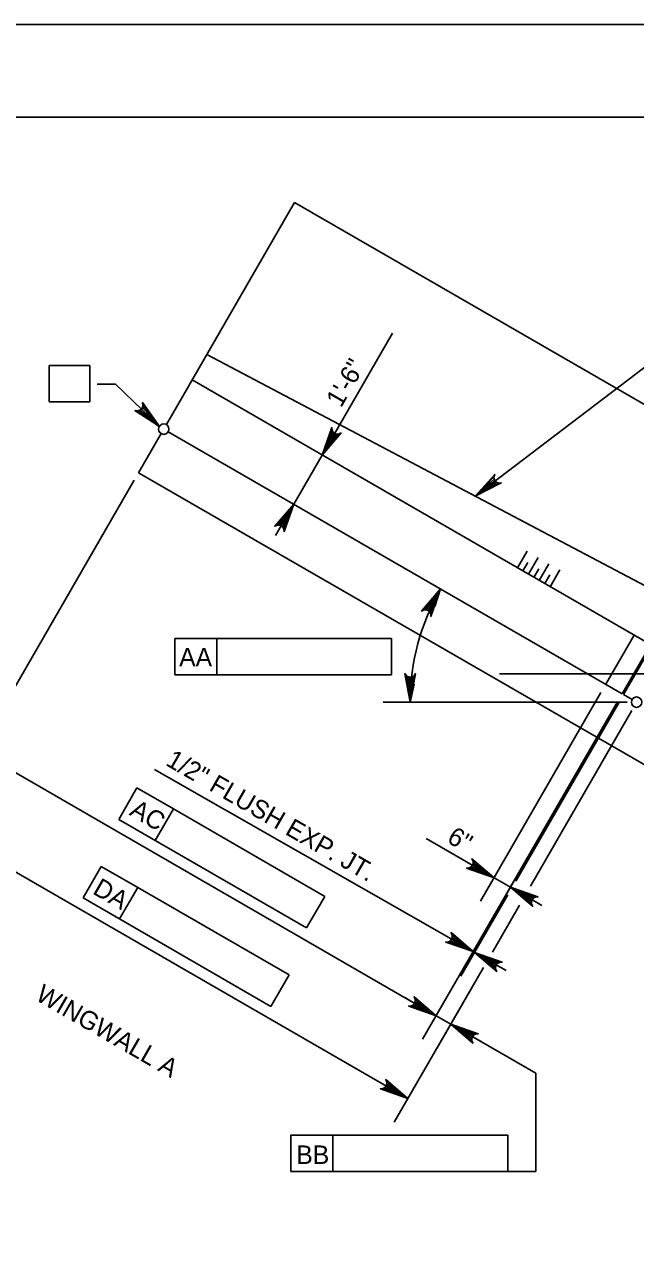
# Model space of a CAD drawing. Extents: x 638255 to 640306, y 296059 to 298435.
# Drawn here: x 638520.2 to 638619.4, y 298235.1 to 298435.5 of the extents above; entities that cross this region are included whole.
import ezdxf

# ---------------------------------------------------------------- set-up
doc = ezdxf.new("R2010")
doc.units = 0
for name, color, linetype in [('2', 7, 'Continuous'), ('Level 10', 7, 'Continuous'), ('Level 2', 7, 'Continuous'), ('Level 3', 7, 'Continuous'), ('PLT-BNDY', 7, 'Continuous')]:
    doc.layers.add(name, color=color, linetype=linetype)

msp = doc.modelspace()

# ---------------------------------------------------------------- linework, layer by layer
at = {"layer": '2'}
msp.add_line((638475.46, 298420.46), (639261.46, 298420.46), dxfattribs=at)
at = {"layer": 'Level 10'}
for p, q in [((638543.25, 298370.52), (638564.06, 298406.56)), ((638646.07, 298359.21), (638564.06, 298406.56)), ((638625.9, 298341.75), (638549.83, 298381.91)), ((638621.87, 298334.78), (638547.43, 298377.76)), ((638538.73, 298362.69), (638542.4, 298369.05)), ((638617.26, 298326.8), (638543.56, 298369.36)), ((638621.86, 298314.7), (638538.73, 298362.69)), ((638625.9, 298341.75), (638617.26, 298326.8)), ((638625.6, 298340.74), (638617.48, 298326.67)), ((638619.21, 298336.31), (638614.6, 298328.34)), ((638597.38, 298330.05), (638862.07, 298330.05)), ((638618.89, 298325.87), (638617.48, 298326.67))]:
    msp.add_line(p, q, dxfattribs=at)
at = {"layer": 'Level 2'}
for p, q in [((638600.27, 298347.25), (638601.85, 298349.98)), ((638602.05, 298346.22), (638603.62, 298348.95)), ((638601.16, 298346.74), (638601.97, 298348.14)), ((638602.93, 298345.71), (638603.74, 298347.11)), ((638603.82, 298345.2), (638605.39, 298347.93)), ((638604.7, 298344.69), (638605.51, 298346.09)), ((638605.59, 298344.18), (638607.17, 298346.91))]:
    msp.add_line(p, q, dxfattribs=at)
at = {"layer": 'Level 3'}
for p, q in [((638568.54, 298365.57), (638579.97, 298385.34)), ((638524.23, 298374.2), (638524.23, 298380.1)), ((638524.23, 298380.1), (638530.81, 298380.1)), ((638530.81, 298374.2), (638530.81, 298380.1)), ((638593.4, 298358.91), (638622.1, 298380.72)), ((638534.96, 298377.07), (638532.01, 298377.07)), ((638542.11, 298370.23), (638534.96, 298377.07)), ((638530.81, 298374.2), (638524.23, 298374.2)), ((638563.94, 298357.59), (638568.54, 298365.56)), ((638538.04, 298361.51), (638510.43, 298313.67)), ((638563.94, 298357.59), (638560.99, 298352.49)), ((638544.6, 298335.8), (638551.43, 298335.8)), ((638544.6, 298329.9), (638544.6, 298335.8)), ((638551.43, 298329.9), (638551.43, 298335.8)), ((638551.43, 298335.8), (638579.83, 298335.8)), ((638579.83, 298335.8), (638579.83, 298329.9)), ((638579.83, 298329.9), (638544.6, 298329.9)), ((638613.84, 298327.01), (638594.26, 298293.1)), ((638618.09, 298325.44), (638578.44, 298325.44)), ((638616.5, 298325.47), (638584.87, 298270.69)), ((638616.5, 298325.47), (638590.88, 298281.1)), ((638616.5, 298325.47), (638596.92, 298291.56)), ((638616.72, 298325.35), (638599.99, 298296.36)), ((638618.86, 298324.11), (638602.37, 298295.55)), ((638512.64, 298317.5), (638587.08, 298274.52)), ((638587.98, 298287.87), (638541.33, 298314.5)), ((638535.51, 298306.41), (638538.46, 298311.52)), ((638538.46, 298311.52), (638544.38, 298308.1)), ((638541.43, 298302.99), (638544.38, 298308.1)), ((638544.38, 298308.1), (638568.97, 298293.9)), ((638505.66, 298305.42), (638582.47, 298261.08)), ((638566.02, 298288.79), (638535.51, 298306.41)), ((638591.37, 298299.87), (638585.43, 298303.3)), ((638593.92, 298298.4), (638591.37, 298299.87)), ((638529.72, 298293.66), (638532.67, 298298.76)), ((638532.67, 298298.76), (638538.59, 298295.34)), ((638599.13, 298295.39), (638596.47, 298296.93)), ((638535.64, 298290.24), (638538.59, 298295.34)), ((638538.59, 298295.34), (638563.18, 298281.14)), ((638560.23, 298276.04), (638529.72, 298293.66)), ((638568.97, 298293.9), (638566.02, 298288.79)), ((638598.72, 298294.17), (638591.1, 298280.97)), ((638601.68, 298293.92), (638604.23, 298292.44)), ((638600.58, 298292.46), (638596.19, 298284.86)), ((638590.53, 298286.4), (638587.98, 298287.87)), ((638593.31, 298284.8), (638593.09, 298284.93)), ((638595.86, 298283.32), (638598.41, 298281.85)), ((638563.18, 298281.14), (638560.23, 298276.04)), ((638594.76, 298282.37), (638587.23, 298269.33)), ((638592.76, 298278.91), (638580.26, 298257.25)), ((638584.53, 298275.99), (638581.97, 298277.47)), ((638587.08, 298274.52), (638589.44, 298273.16)), ((638589.44, 298273.16), (638603.28, 298265.17)), ((638591.99, 298271.68), (638594.54, 298270.21)), ((638603.28, 298265.17), (638603.28, 298249.24)), ((638563.45, 298255.14), (638570.29, 298255.14)), ((638563.45, 298249.24), (638563.45, 298255.14)), ((638570.29, 298249.24), (638570.29, 298255.14)), ((638570.29, 298255.14), (638598.69, 298255.14)), ((638598.69, 298255.14), (638598.69, 298249.24)), ((638598.69, 298249.24), (638563.45, 298249.24)), ((638603.28, 298249.24), (638598.69, 298249.24))]:
    msp.add_line(p, q, dxfattribs=at)
for points in [[(638542.11, 298370.23), (638538.14, 298372.82), (638538.57, 298372.75), (638538.92, 298372.85), (638539.18, 298373.03), (638539.35, 298373.3), (638539.44, 298373.65), (638539.35, 298374.08), (638542.11, 298370.23), (638539.44, 298373.65), (638539.35, 298373.3), (638542.11, 298370.23), (638539.18, 298373.03), (638538.92, 298372.85), (638542.11, 298370.23), (638538.57, 298372.75)], [(638568.54, 298365.57), (638570.11, 298370.03), (638570.15, 298369.6), (638570.33, 298369.28), (638570.57, 298369.08), (638570.87, 298368.97), (638571.23, 298368.97), (638571.63, 298369.16), (638568.54, 298365.57), (638571.23, 298368.97), (638570.87, 298368.97), (638568.54, 298365.57), (638570.57, 298369.08), (638570.33, 298369.28), (638568.54, 298365.57), (638570.15, 298369.6)], [(638593.4, 298358.91), (638596.57, 298362.42), (638596.44, 298362.01), (638596.48, 298361.65), (638596.63, 298361.36), (638596.86, 298361.15), (638597.19, 298361.01), (638597.63, 298361.03), (638593.4, 298358.91), (638597.19, 298361.01), (638596.86, 298361.15), (638593.4, 298358.91), (638596.63, 298361.36), (638596.48, 298361.65), (638593.4, 298358.91), (638596.44, 298362.01)], [(638563.94, 298357.59), (638562.37, 298353.13), (638562.33, 298353.56), (638562.16, 298353.88), (638561.91, 298354.08), (638561.61, 298354.19), (638561.25, 298354.18), (638560.86, 298354), (638563.94, 298357.59), (638561.25, 298354.18), (638561.61, 298354.19), (638563.94, 298357.59), (638561.91, 298354.08), (638562.16, 298353.88), (638563.94, 298357.59), (638562.33, 298353.56)], [(638587.78, 298343.83), (638586.21, 298339.36), (638586.18, 298339.8), (638586, 298340.11), (638585.76, 298340.31), (638585.46, 298340.42), (638585.1, 298340.42), (638584.7, 298340.23), (638587.78, 298343.83), (638585.1, 298340.42), (638585.46, 298340.42), (638587.78, 298343.83), (638585.76, 298340.31), (638586, 298340.11), (638587.78, 298343.83), (638586.18, 298339.8)], [(638582.86, 298325.44), (638581.98, 298330.09), (638582.23, 298329.73), (638582.55, 298329.55), (638582.86, 298329.5), (638583.17, 298329.55), (638583.48, 298329.73), (638583.73, 298330.09), (638582.86, 298325.44), (638583.48, 298329.73), (638583.17, 298329.55), (638582.86, 298325.44), (638582.86, 298329.5), (638582.55, 298329.55), (638582.86, 298325.44), (638582.23, 298329.73)], [(638596.47, 298296.93), (638592, 298298.49), (638592.44, 298298.53), (638592.76, 298298.71), (638592.96, 298298.95), (638593.07, 298299.25), (638593.06, 298299.61), (638592.88, 298300.01), (638596.47, 298296.93), (638593.06, 298299.61), (638593.07, 298299.25), (638596.47, 298296.93), (638592.96, 298298.95), (638592.76, 298298.71), (638596.47, 298296.93), (638592.44, 298298.53)], [(638599.13, 298295.39), (638603.59, 298293.82), (638603.16, 298293.79), (638602.84, 298293.61), (638602.64, 298293.36), (638602.53, 298293.07), (638602.53, 298292.7), (638602.72, 298292.31), (638599.13, 298295.39), (638602.53, 298292.7), (638602.53, 298293.07), (638599.13, 298295.39), (638602.64, 298293.36), (638602.84, 298293.61), (638599.13, 298295.39), (638603.16, 298293.79)], [(638593.09, 298284.93), (638588.62, 298286.49), (638589.06, 298286.53), (638589.37, 298286.71), (638589.57, 298286.95), (638589.68, 298287.25), (638589.68, 298287.61), (638589.49, 298288.01), (638593.09, 298284.93), (638589.68, 298287.61), (638589.68, 298287.25), (638593.09, 298284.93), (638589.57, 298286.95), (638589.37, 298286.71), (638593.09, 298284.93), (638589.06, 298286.53)], [(638593.31, 298284.8), (638597.77, 298283.23), (638597.34, 298283.19), (638597.02, 298283.01), (638596.82, 298282.77), (638596.71, 298282.47), (638596.71, 298282.11), (638596.9, 298281.71), (638593.31, 298284.8), (638596.71, 298282.11), (638596.71, 298282.47), (638593.31, 298284.8), (638596.82, 298282.77), (638597.02, 298283.01), (638593.31, 298284.8), (638597.34, 298283.19)], [(638587.08, 298274.52), (638582.61, 298276.09), (638583.05, 298276.13), (638583.36, 298276.3), (638583.57, 298276.55), (638583.68, 298276.84), (638583.67, 298277.2), (638583.49, 298277.6), (638587.08, 298274.52), (638583.67, 298277.2), (638583.68, 298276.84), (638587.08, 298274.52), (638583.57, 298276.55), (638583.36, 298276.3), (638587.08, 298274.52), (638583.05, 298276.13)], [(638589.44, 298273.16), (638593.9, 298271.59), (638593.47, 298271.55), (638593.15, 298271.37), (638592.95, 298271.13), (638592.84, 298270.83), (638592.84, 298270.47), (638593.03, 298270.07), (638589.44, 298273.16), (638592.84, 298270.47), (638592.84, 298270.83), (638589.44, 298273.16), (638592.95, 298271.13), (638593.15, 298271.37), (638589.44, 298273.16), (638593.47, 298271.55)], [(638582.47, 298261.08), (638578, 298262.65), (638578.44, 298262.69), (638578.75, 298262.87), (638578.95, 298263.11), (638579.06, 298263.41), (638579.06, 298263.77), (638578.87, 298264.16), (638582.47, 298261.08), (638579.06, 298263.77), (638579.06, 298263.41), (638582.47, 298261.08), (638578.95, 298263.11), (638578.75, 298262.87), (638582.47, 298261.08), (638578.44, 298262.69)]]:
    msp.add_lwpolyline(points, dxfattribs=at)
for points in [[(638540.32, 298372.63), (638539.64, 298371.92), (638542.1, 298370.23)], [(638569.59, 298368.36), (638570.44, 298367.87), (638568.54, 298365.56)], [(638596.29, 298360.48), (638595.69, 298361.28), (638593.6, 298359.07)], [(638562.04, 298355.28), (638562.89, 298354.79), (638563.94, 298357.59)], [(638585.98, 298341.44), (638586.85, 298340.99), (638587.78, 298343.82)], [(638583.47, 298328.37), (638582.49, 298328.4), (638582.86, 298325.44)], [(638594.16, 298298.82), (638593.67, 298297.97), (638596.47, 298296.93)], [(638601.93, 298294.34), (638601.43, 298293.49), (638599.13, 298295.39)], [(638590.78, 298286.82), (638590.29, 298285.97), (638593.09, 298284.93)], [(638596.1, 298283.75), (638595.61, 298282.9), (638593.31, 298284.8)], [(638584.77, 298276.42), (638584.28, 298275.57), (638587.08, 298274.52)], [(638592.24, 298272.11), (638591.74, 298271.26), (638589.44, 298273.16)], [(638580.16, 298262.98), (638579.67, 298262.13), (638582.47, 298261.08)]]:
    msp.add_lwpolyline(points, close=True, dxfattribs=at)
for centre in [(638542.82, 298369.78), (638619.62, 298325.44)]:
    msp.add_circle(centre, 0.849, dxfattribs=at)
for start, end in [(149.9988, 180), (174.95, 175.4061)]:
    msp.add_arc((638619.62, 298325.44), 36.77, start, end, dxfattribs=at)
at = {"layer": 'PLT-BNDY'}
msp.add_lwpolyline([(638435.46, 298435.46), (639276.46, 298435.46), (639276.46, 297841.46), (638435.46, 297841.46)], close=True, dxfattribs=at)

# ---------------------------------------------------------------- texts
at = {"layer": 'Level 3'}
for s, height, rotation, p in [('1\'-6"', 3, 60, (638571.62, 298373.13)), ('1/2" FLUSH EXP. JT.', 3.0001, 330, (638542.98, 298315.29)), ('AC', 3, 330, (638537.08, 298307.2)), ('6"', 3, 330, (638588.65, 298302.78)), ('DA', 3, 330.0005, (638531.1, 298294.42)), ('WINGWALL A', 3, 330.0005, (638521.8, 298277.18))]:
    msp.add_text(s, height=height, rotation=rotation, dxfattribs=at).set_placement(p)
for s, p in [('AA', (638545.32, 298331.25)), ('BB', (638564.35, 298250.45))]:
    msp.add_text(s, height=3, dxfattribs=at).set_placement(p)

doc.saveas('drawing.dxf')
